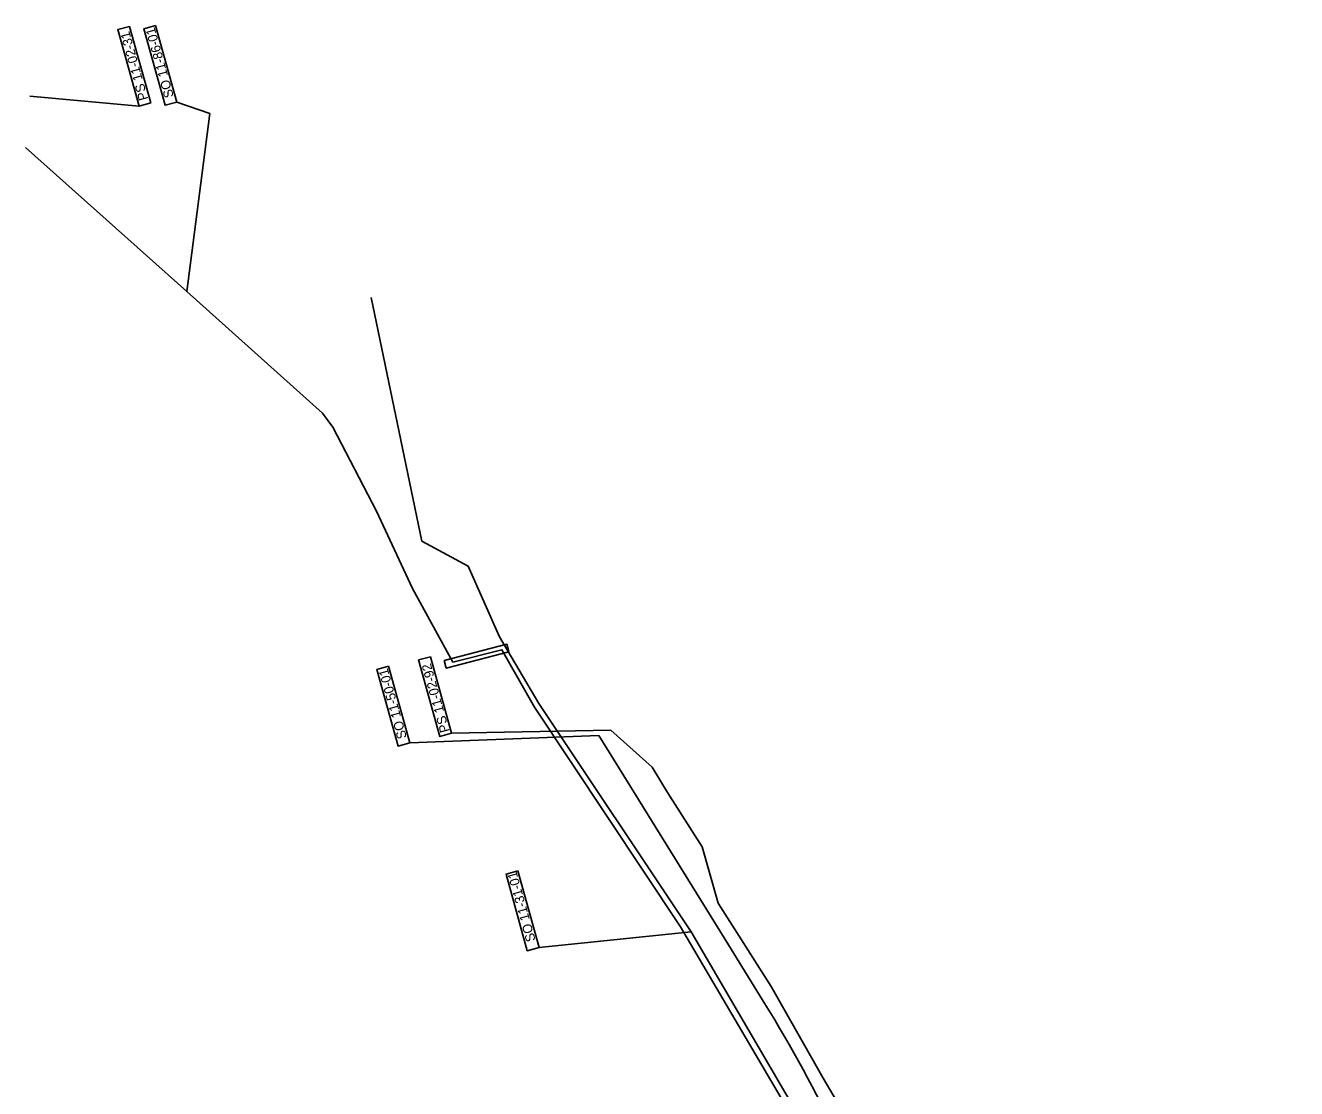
# Model space of a CAD drawing. Extents: x -820988 to -820703, y -1070846 to -1070074.
# Drawn here: x -820988.3 to -820759.6, y -1070265.6 to -1070074.4 of the extents above; entities that cross this region are included whole.
import ezdxf

# ---------------------------------------------------------------- set-up
doc = ezdxf.new("R2010")
doc.units = 0
for name, color, linetype in [('_PS_SO_číslo', 7, 'Continuous'), ('PS-11-02-31', 7, 'Continuous'), ('PS-11-02-41', 7, 'Continuous'), ('PS-11-02-92', 7, 'Continuous'), ('SO-11-31-01', 7, 'Continuous'), ('SO-11-50-01', 7, 'Continuous'), ('SO-11-86-01', 7, 'Continuous')]:
    doc.layers.add(name, color=color, linetype=linetype)

msp = doc.modelspace()

# ---------------------------------------------------------------- linework, layer by layer
at = {"layer": '_PS_SO_číslo'}
for p, q in [((-820987.51, -1070087.08), (-820967.85, -1070088.89)), ((-820955.09, -1070090.19), (-820961.05, -1070088.13)), ((-820885.11, -1070202.07), (-820919.13, -1070203.37)), ((-820882.99, -1070201.13), (-820911.61, -1070201.67)), ((-820868.5, -1070237.37), (-820895.88, -1070240.18))]:
    msp.add_line(p, q, dxfattribs=at)
for points in [[(-820964.88, -1070074.36), (-820961.05, -1070088.13), (-820963.17, -1070088.72), (-820967, -1070074.95)], [(-820969.56, -1070074.53), (-820965.74, -1070088.3), (-820967.85, -1070088.89), (-820971.68, -1070075.11)], [(-820915.44, -1070187.9), (-820911.61, -1070201.67), (-820913.73, -1070202.26), (-820917.56, -1070188.48)], [(-820922.96, -1070189.59), (-820919.13, -1070203.37), (-820921.25, -1070203.96), (-820925.08, -1070190.18)], [(-820899.71, -1070226.4), (-820895.88, -1070240.18), (-820898, -1070240.77), (-820901.83, -1070226.99)]]:
    msp.add_lwpolyline(points, close=True, dxfattribs=at)
at = {"layer": 'PS-11-02-31'}
for points in [[(-820988.29, -1070096.33), (-820959.28, -1070122.22)], [(-820959.28, -1070122.22), (-820934.84, -1070144.09), (-820933, -1070146.6), (-820925.15, -1070161.74), (-820918.63, -1070175.61), (-820911.37, -1070188.87), (-820902.58, -1070186.65), (-820896.69, -1070196.98), (-820870.46, -1070236.45), (-820846.57, -1070277.08), (-820842.6, -1070282.11), (-820813.47, -1070365.17), (-820809.8, -1070374.33), (-820792.8, -1070426.72), (-820792.34, -1070428.47), (-820790.08, -1070430.86), (-820788.92, -1070435.58), (-820780.39, -1070470.86), (-820770.55, -1070511.61), (-820767.89, -1070524.68), (-820765.3, -1070562.4), (-820759.61, -1070562.18)]]:
    msp.add_lwpolyline(points, dxfattribs=at)
at = {"layer": 'PS-11-02-41'}
msp.add_lwpolyline([(-820882.99, -1070201.13), (-820875.54, -1070207.75), (-820872.79, -1070212.31), (-820866.57, -1070222.1), (-820863.69, -1070232.23), (-820854.15, -1070247.2), (-820844.78, -1070263.71), (-820834.74, -1070280.72), (-820830.77, -1070287.4), (-820826.6, -1070295.78), (-820822.74, -1070307.42), (-820822.4, -1070310.54), (-820820.82, -1070316.36), (-820815.08, -1070335.82), (-820806.04, -1070362.21), (-820801.05, -1070374.78), (-820795.98, -1070387.28), (-820794.84, -1070388), (-820792.15, -1070393.19), (-820783.48, -1070412.23), (-820783.6, -1070416.46), (-820783.6, -1070418.02), (-820782.43, -1070424.35)], dxfattribs=at)
at = {"layer": 'PS-11-02-92'}
msp.add_lwpolyline([(-820882.99, -1070201.13), (-820875.54, -1070207.75), (-820872.79, -1070212.31), (-820866.57, -1070222.1), (-820863.69, -1070232.23), (-820854.15, -1070247.2), (-820844.78, -1070263.71), (-820834.74, -1070280.72), (-820830.77, -1070287.4), (-820826.6, -1070295.78), (-820822.74, -1070307.42), (-820822.4, -1070310.54), (-820820.82, -1070316.36), (-820815.08, -1070335.82), (-820806.04, -1070362.21), (-820801.05, -1070374.78), (-820795.98, -1070387.28), (-820794.84, -1070388), (-820792.15, -1070393.19), (-820783.48, -1070412.23), (-820783.6, -1070416.46), (-820783.6, -1070418.02), (-820782.43, -1070424.35)], dxfattribs=at)
at = {"layer": 'SO-11-31-01'}
msp.add_lwpolyline([(-820926.07, -1070123.29), (-820916.95, -1070167.12), (-820908.61, -1070171.6), (-820902.99, -1070184.31), (-820895.92, -1070196.33), (-820868.5, -1070237.37), (-820845.66, -1070276.46), (-820841.66, -1070281.51), (-820839.82, -1070285.2), (-820808.13, -1070374.18), (-820790.33, -1070426.97), (-820782.93, -1070433.41), (-820769.19, -1070488.5), (-820779.89, -1070491.4)], dxfattribs=at)
at = {"layer": 'SO-11-50-01'}
msp.add_lwpolyline([(-820885.11, -1070202.07), (-820878.77, -1070212.32), (-820861.83, -1070239.7), (-820855.27, -1070250.3)], dxfattribs=at)
msp.add_arc((-821067.95, -1070381.86), 250.08, 19.1742, 31.7407, dxfattribs=at)
at = {"layer": 'SO-11-86-01'}
for points in [[(-820955.09, -1070090.19), (-820959.28, -1070122.22), (-820934.84, -1070144.09), (-820933, -1070146.6), (-820925.15, -1070161.74), (-820918.63, -1070175.61), (-820911.37, -1070188.87), (-820902.58, -1070186.65), (-820896.69, -1070196.98), (-820870.46, -1070236.45), (-820846.57, -1070277.08)], [(-820882.99, -1070201.13), (-820875.54, -1070207.75), (-820872.79, -1070212.31), (-820866.57, -1070222.1), (-820863.69, -1070232.23), (-820854.15, -1070247.2), (-820844.78, -1070263.71), (-820834.74, -1070280.72)]]:
    msp.add_lwpolyline(points, dxfattribs=at)
msp.add_lwpolyline([(-820912.95, -1070188.59), (-820912.59, -1070189.95), (-820901.35, -1070187), (-820901.71, -1070185.64)], close=True, dxfattribs=at)

# ---------------------------------------------------------------- texts
at = {"layer": '_PS_SO_číslo'}
for s, p in [('PS 11-02-31', (-820966.19, -1070087.59)), ('SO 11-86-01', (-820961.58, -1070087.13)), ('SO 11-50-01', (-820919.65, -1070202.42)), ('PS 11-02-92', (-820911.97, -1070201.28)), ('SO 11-31-01', (-820896.49, -1070238.9))]:
    msp.add_text(s, height=1.7, rotation=105.5289, dxfattribs=at).set_placement(p)

doc.saveas('drawing.dxf')
